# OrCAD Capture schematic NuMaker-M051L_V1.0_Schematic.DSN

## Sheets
1 Nu-Link2-Me: size A3; title: Nu-Link2-Me; rev: 1.0; company: CMHuang; note: Nu-Link2-Me
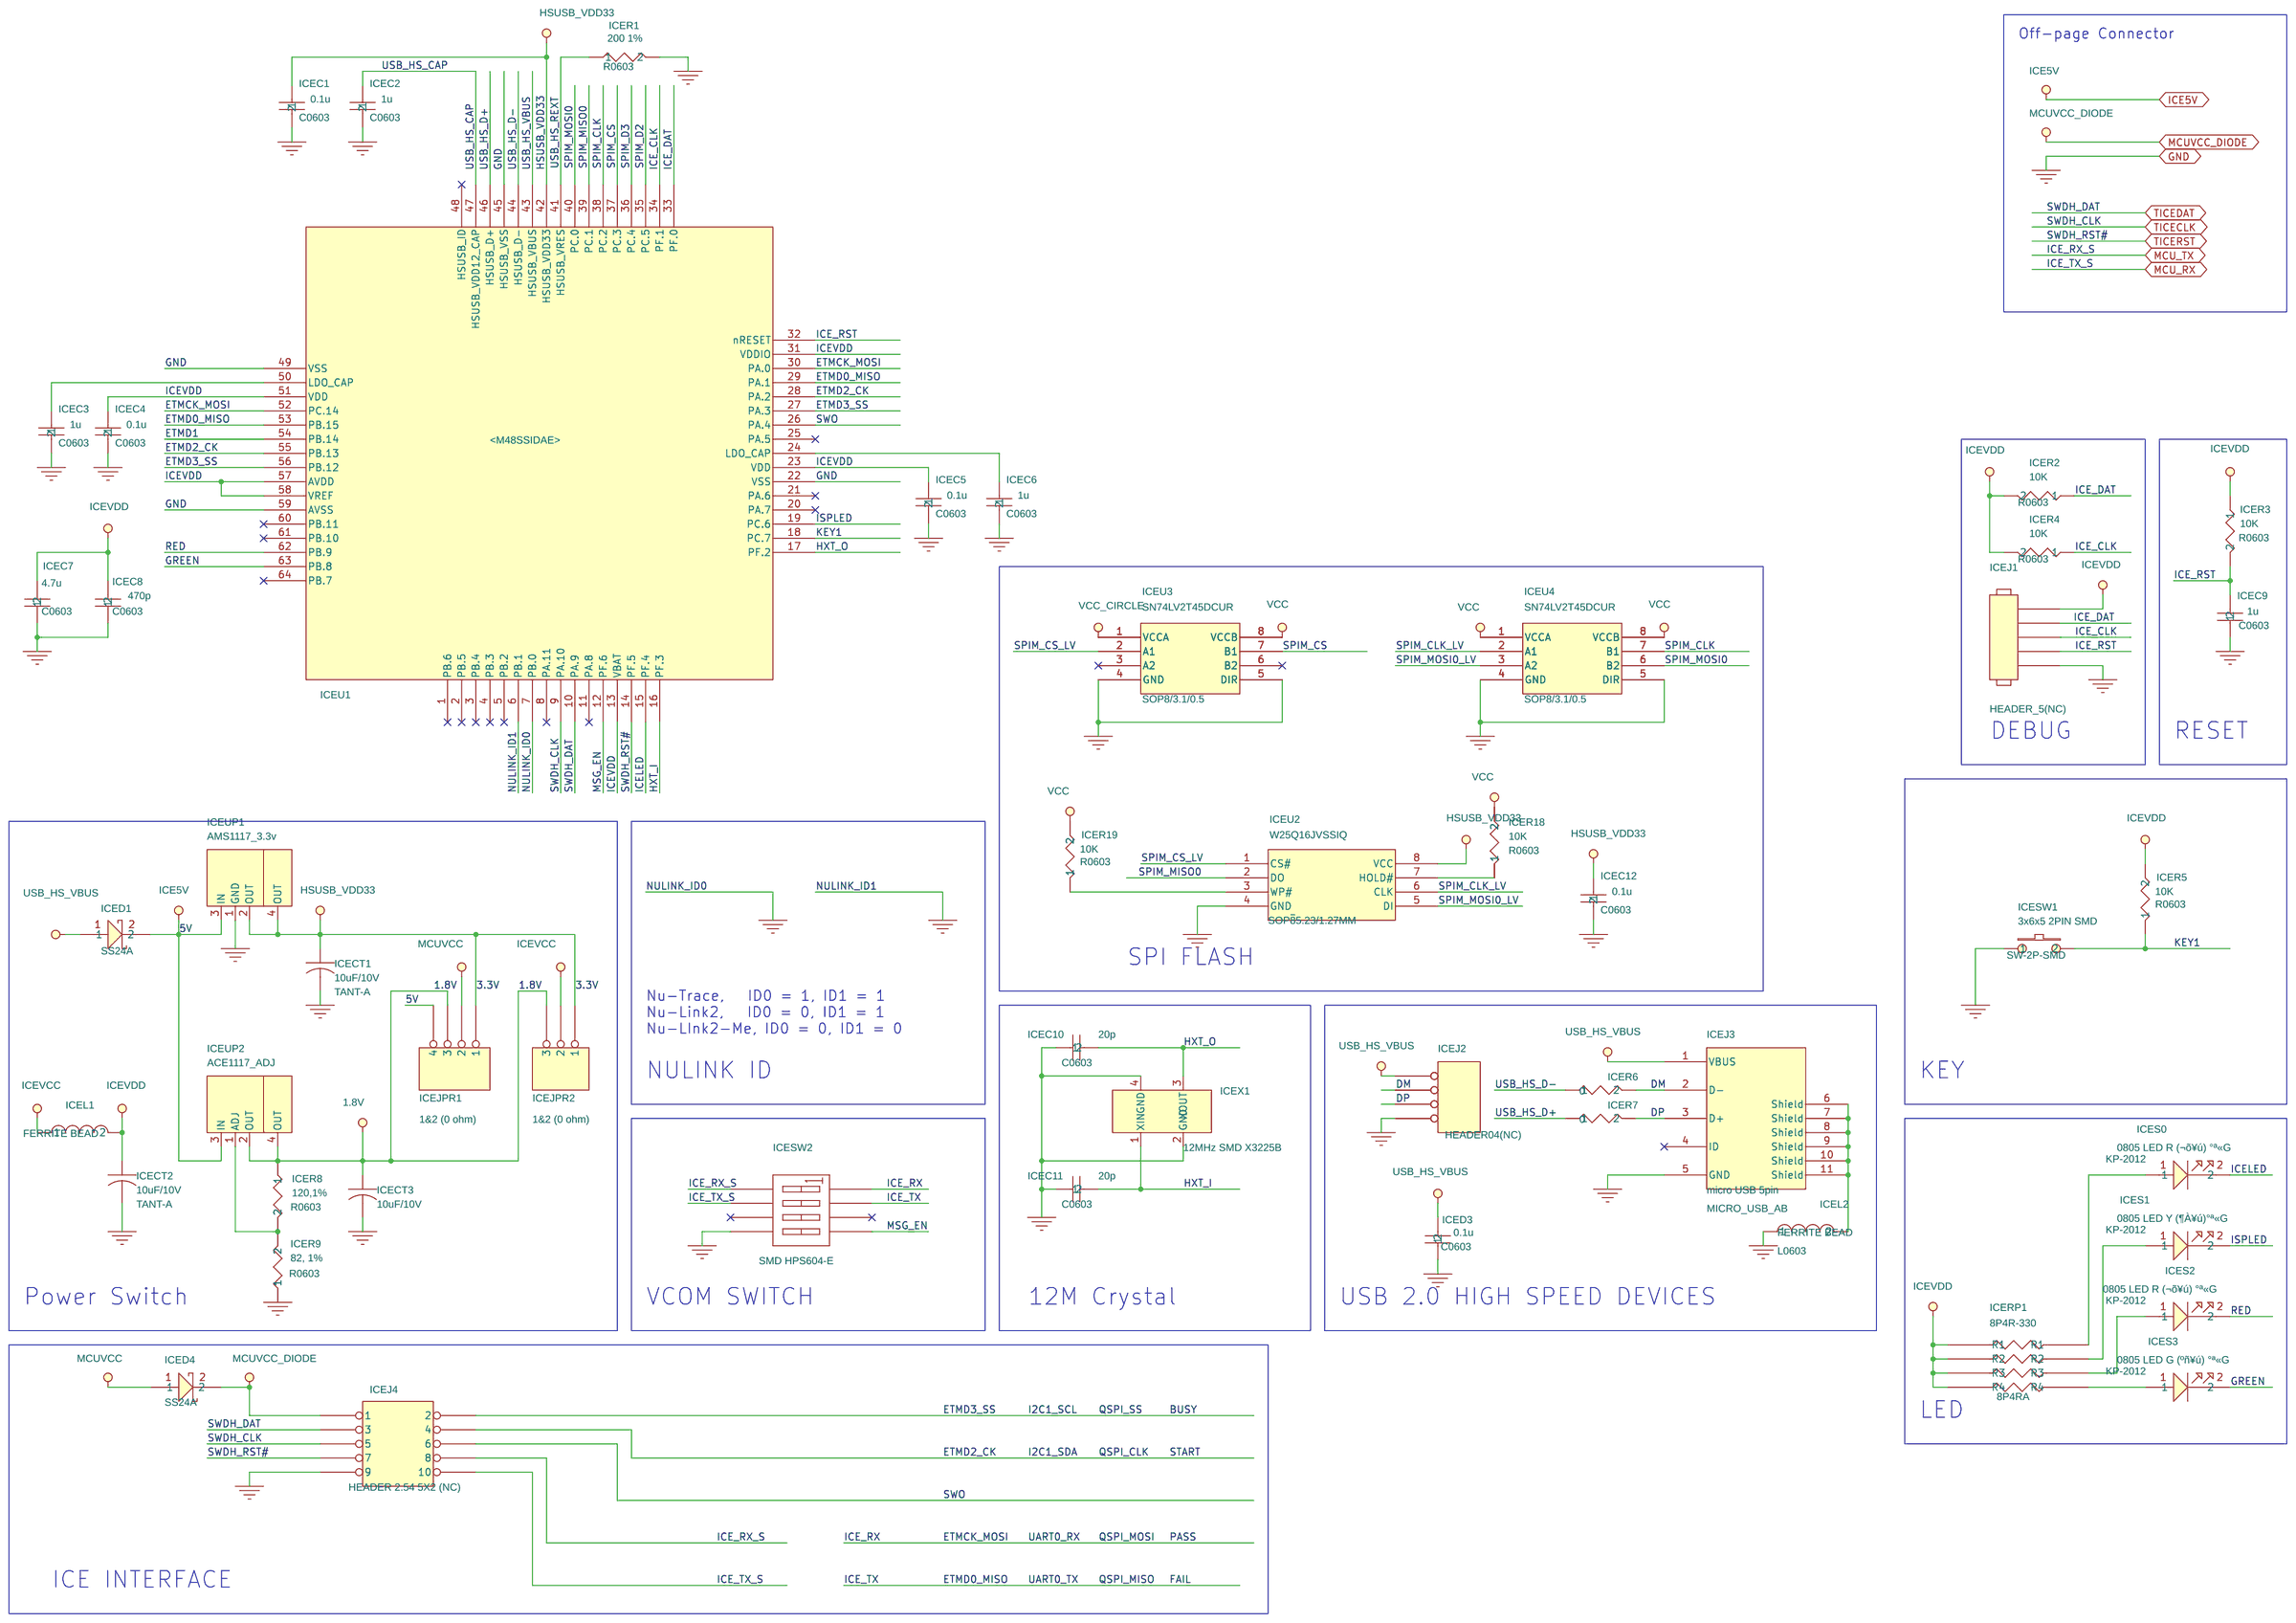
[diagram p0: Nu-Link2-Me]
2 M0516LDN: size Custom; title: M0516LDN; rev: v1.0; note: NuMaker-M051L
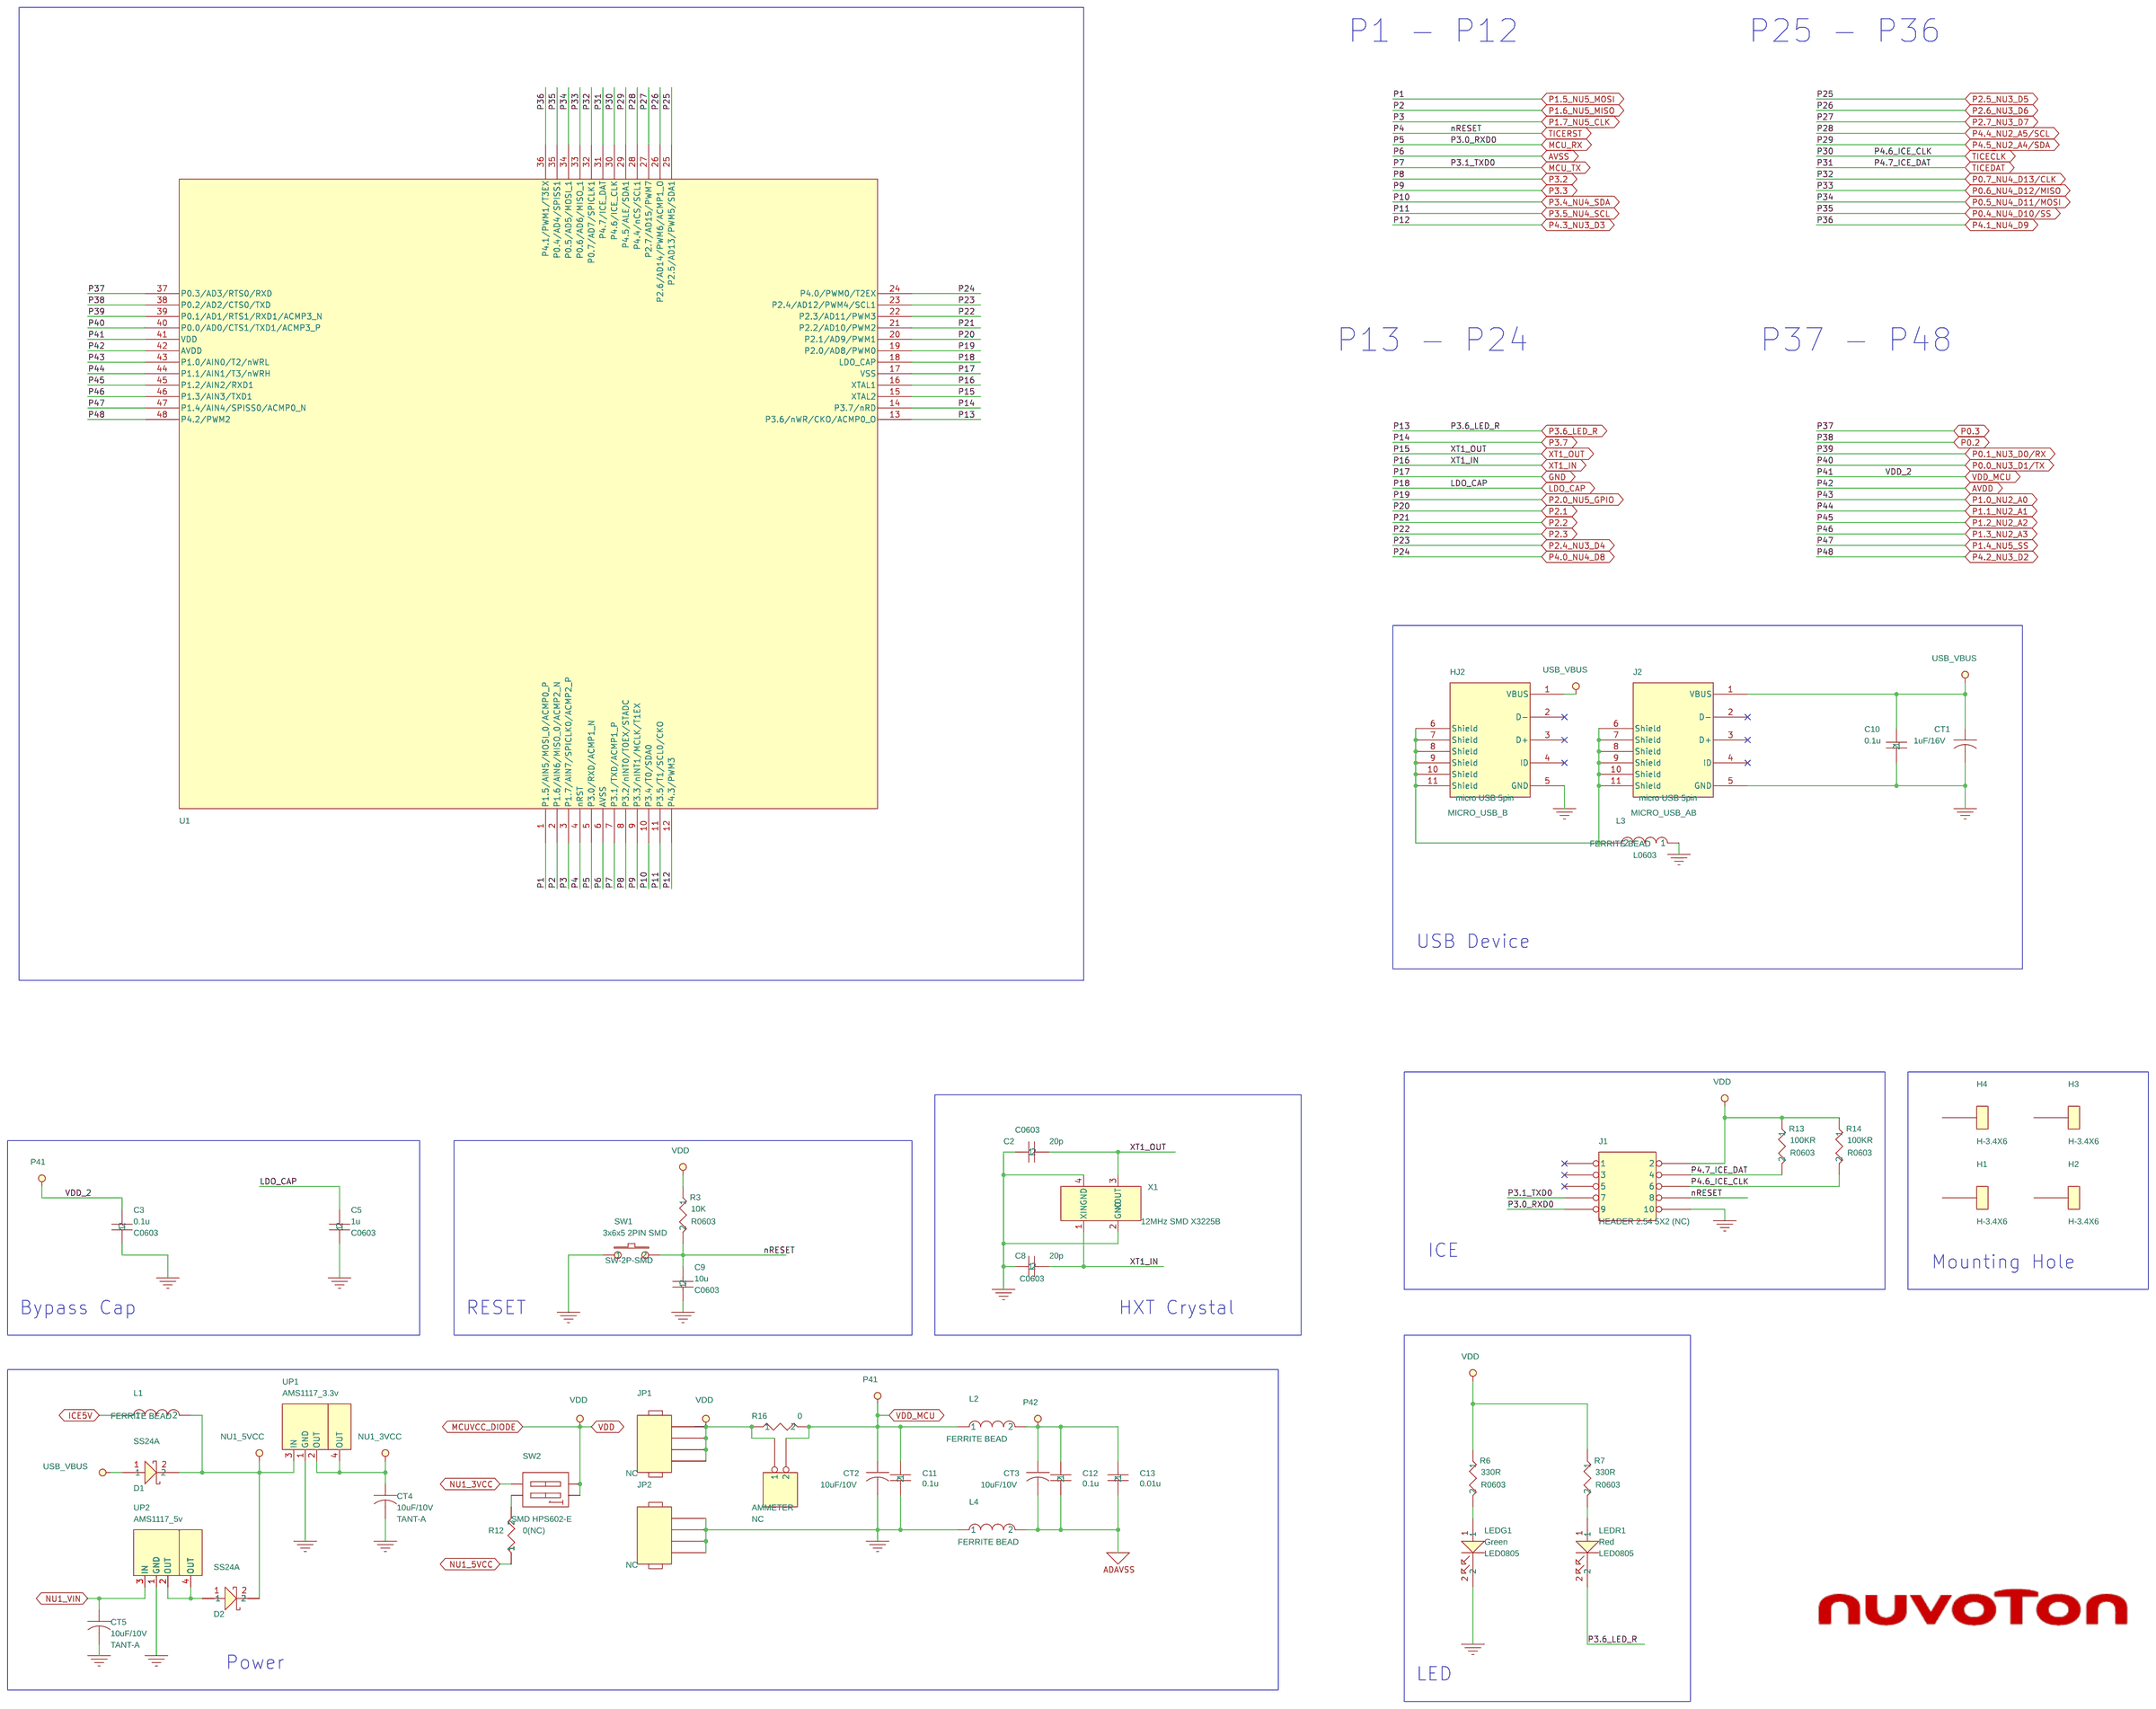
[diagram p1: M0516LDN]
3 Ext. Connector: size Custom; title: Ext. Connector; rev: v1.0; note: NuMaker-M051L
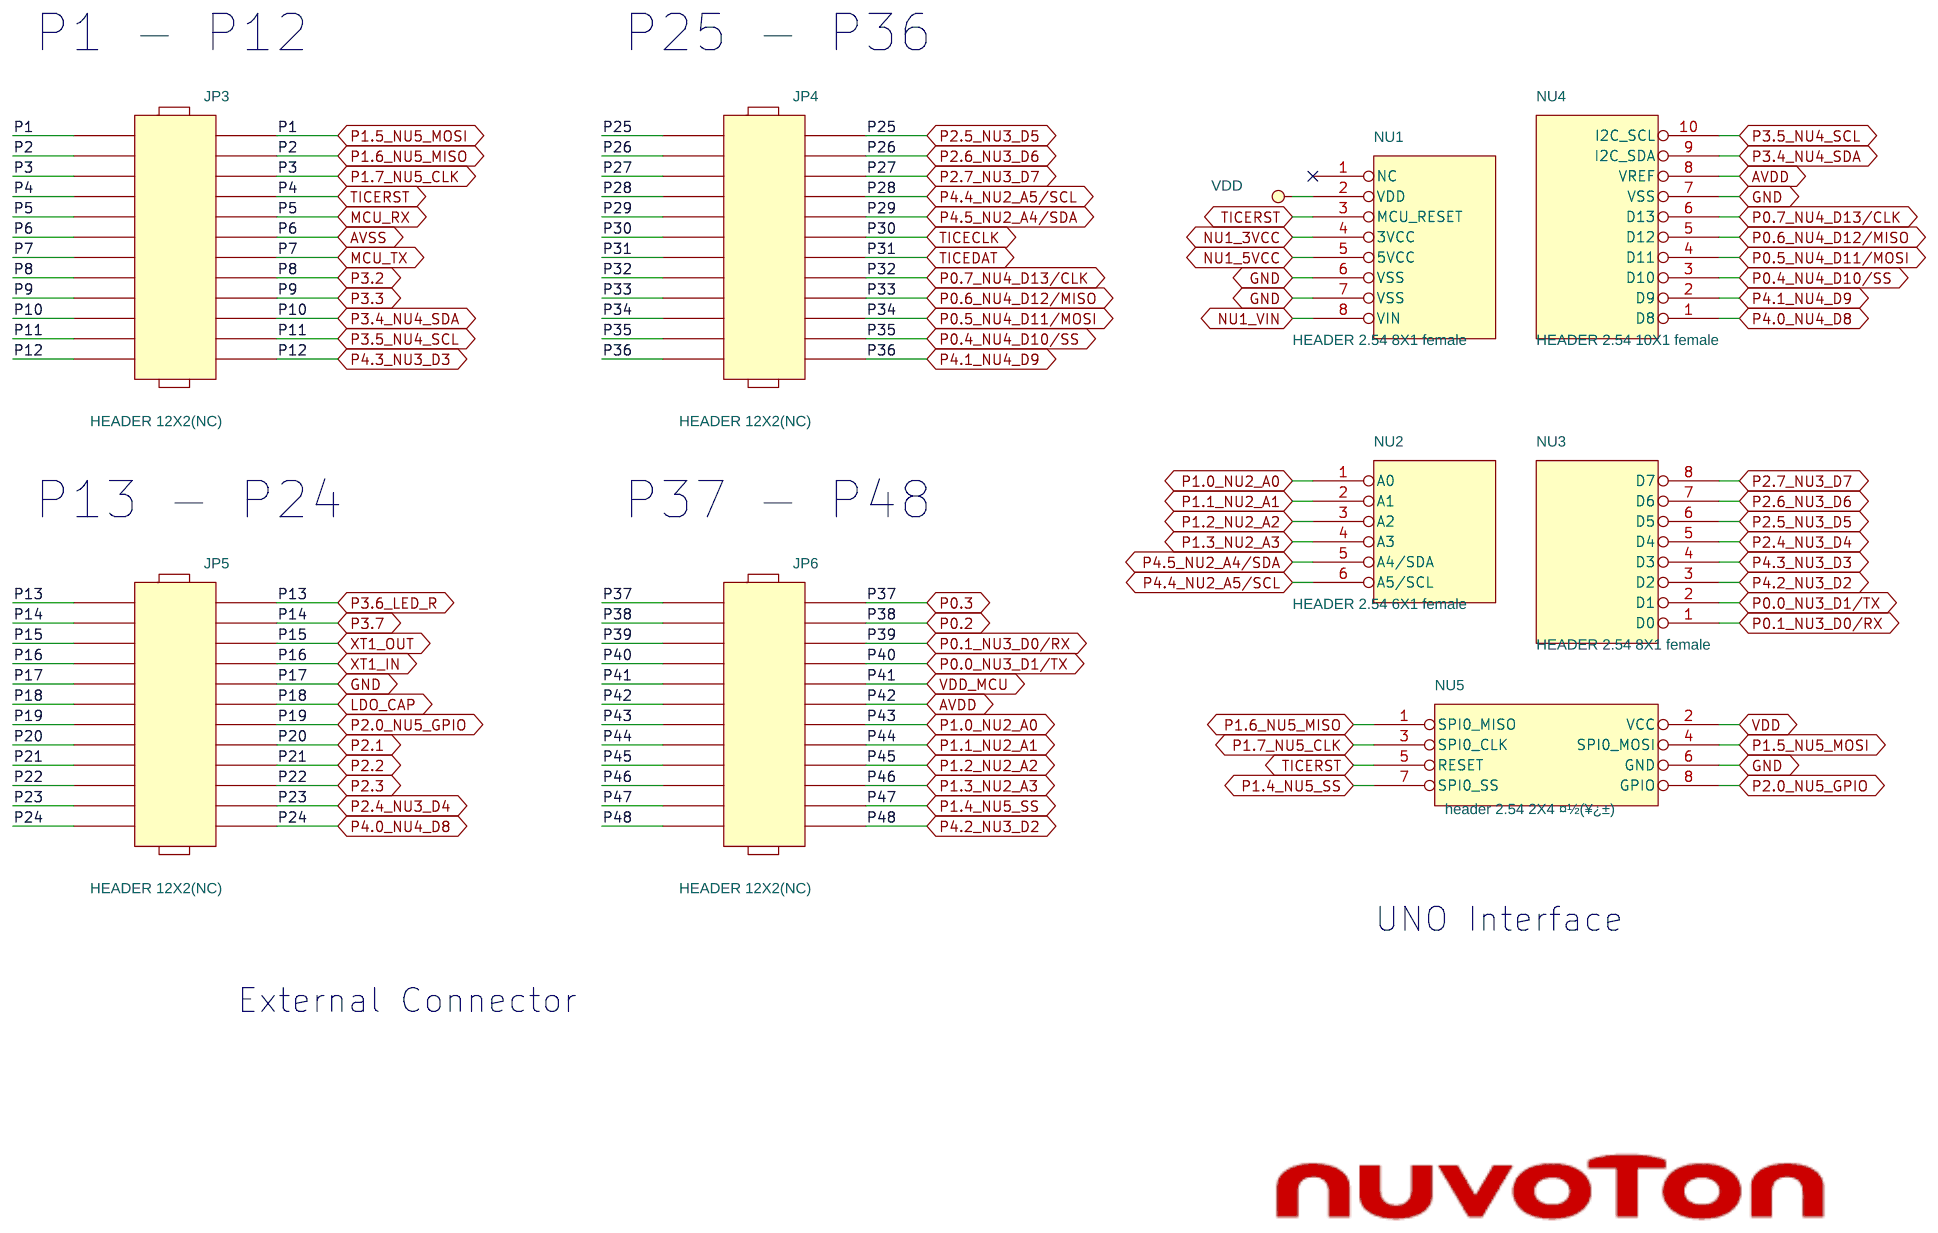
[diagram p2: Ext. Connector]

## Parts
sheet Ext. Connector
JP3  HEADER 12X2(NC)  [HEADER12x2/2.54]
JP4  HEADER 12X2(NC)  [HEADER12x2/2.54]
JP5  HEADER 12X2(NC)  [HEADER12x2/2.54]
JP6  HEADER 12X2(NC)  [HEADER12x2/2.54]
NU1  HEADER 2.54 8X1 female  [SIP-8P]
NU2  HEADER 2.54 6X1 female  [SIP-6P]
NU3  HEADER 2.54 8X1 female  [SIP-8P]
NU4  HEADER 2.54 10X1 female  [SIP-10P]
NU5  header 2.54 2X4 ¤½(¥¿­±)  [HEADER4X2]
sheet M0516LDN
AMMETER  NC  [HEADER2X1]
C2  20p  [C0603]
C3  0.1u  [C0603]
C5  1u  [C0603]
C8  20p  [C0603]
C9  10u  [C0603]
C10  0.1u  [C0603]
C11  0.1u  [C0603]
C12  0.1u  [C0603]
C13  0.01u  [C0603]
CT1  1uF/16V  [TANT-A]
CT2  10uF/10V  [TANT-A]
CT3  10uF/10V  [TANT-A]
CT4  10uF/10V  [TANT-A]
CT5  10uF/10V  [TANT-A]
D1  SS24A  [RB060L]
D2  SS24A  [RB060L]
H1  H-3.4X6  [H-3.4X6]
H2  H-3.4X6  [H-3.4X6]
H3  H-3.4X6  [H-3.4X6]
H4  H-3.4X6  [H-3.4X6]
HJ2  micro USB 5pin  [MICRO_USB_B]
J1  HEADER 2.54 5X2 (NC)  [HEADER5X2]
J2  micro USB 5pin  [MICRO_USB_AB]
JP1  NC  [header1x4]
JP2  NC  [header1x4]
L1  FERRITE BEAD  [L0603]
L2  FERRITE BEAD  [L0603]
L3  FERRITE BEAD  [L0603]
L4  FERRITE BEAD  [L0603]
LEDG1  Green  [LED0805]
LEDR1  Red  [LED0805]
R3  10K  [R0603]
R6  330R  [R0603]
R7  330R  [R0603]
R12  0(NC)  [R0603]
R13  100KR  [R0603]
R14  100KR  [R0603]
R16  0  [R0603]
SW1  3x6x5 2PIN SMD  [SW-2P-SMD]
SW2  SMD HPS602-E  [SW1X2]
U1  M0516LDN  [MCU_LQFP48_7X7mm]
UP1  AMS1117_3.3v  [SOT-223-1]
UP2  AMS1117_5v  [SOT-223-1]
X1  12MHz SMD X3225B  [CRYSTAL_SMD]
sheet Nu-Link2-Me
ICEC1  0.1u  [C0603]
ICEC2  1u  [C0603]
ICEC3  1u  [C0603]
ICEC4  0.1u  [C0603]
ICEC5  0.1u  [C0603]
ICEC6  1u  [C0603]
ICEC7  4.7u  [C0603]
ICEC8  470p  [C0603]
ICEC9  1u  [C0603]
ICEC10  20p  [C0603]
ICEC11  20p  [C0603]
ICEC12  0.1u  [C0603]
ICECT1  10uF/10V  [TANT-A]
ICECT2  10uF/10V  [TANT-A]
ICECT3  10uF/10V  [TANT-A]
ICED1  SS24A  [RB060L]
ICED3  0.1u  [C0603]
ICED4  SS24A  [RB060L]
ICEJ1  HEADER_5(NC)  [HEADER5X1]
ICEJ2  HEADER04(NC)  [HEADER04]
ICEJ3  micro USB 5pin  [MICRO_USB_AB]
ICEJ4  HEADER 2.54 5X2 (NC)  [HEADER5X2]
ICEJPR1  1&2 (0 ohm)  [R0603X3]
ICEJPR2  1&2 (0 ohm)  [R0603X2]
ICEL1  FERRITE BEAD  [L0603]
ICEL2  FERRITE BEAD  [L0603]
ICER1  200 1%  [R0603]
ICER2  10K  [R0603]
ICER3  10K  [R0603]
ICER4  10K  [R0603]
ICER5  10K  [R0603]
ICER6  0  [R0603]
ICER7  0  [R0603]
ICER8  120,1%  [R0603]
ICER9  82, 1%  [R0603]
ICER18  10K  [R0603]
ICER19  10K  [R0603]
ICERP1  8P4R-330  [8P4RA]
ICES0  0805 LED R (¬õ¥ú) °ª«G  [KP-2012]
ICES1  0805 LED Y (¶À¥ú)°ª«G  [KP-2012]
ICES2  0805 LED R (¬õ¥ú) °ª«G  [KP-2012]
ICES3  0805 LED G (ºñ¥ú) °ª«G  [KP-2012]
ICESW1  3x6x5 2PIN SMD  [SW-2P-SMD]
ICESW2  SMD HPS604-E  [SW1X4]
ICEU1  M48SSIDAE  [LQFP64_7x7_M48SSIDAE]
ICEU2  W25Q16JVSSIQ  [SOP8\5.23/1.27MM]
ICEU3  SN74LV2T45DCUR  [SOP8/3.1/0.5]
ICEU4  SN74LV2T45DCUR  [SOP8/3.1/0.5]
ICEUP1  AMS1117_3.3v  [SOT-223-1]
ICEUP2  ACE1117_ADJ  [SOT-223-1]
ICEX1  12MHz SMD X3225B  [CRYSTAL_SMD]

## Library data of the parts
JP3-JP6 = HEADER_12X2
NU1 = POWER_CONNECT_0
NU2 = ADC_CONNECT_0
NU3 = PWM0_CONNECT_0
NU4 = PWM1_CONNECT_1
NU5 = NuEdu_NU7
AMMETER = HEADER_2
C2 ICEC7 = CAP-C: Package: 0603
C3 = CAP-C_3: Package: 0603; element_no: C0004
C5 = CAP-C_1: Package: 0603; element_no: C0006
C8 = CAP-C_2: Package: 0603
C9 ICEC6 = CAP-C_4: Package: 0603; element_no: C0006
C10 = C_0.1u: element_no: C0004
C11 = C_0.1u_1: element_no: C0004
C12 = C_0.1u_3: element_no: C0004
C13 = C_0.1u_2: element_no: C0003
CT1 = C_1uF_16V
CT2-CT5 ICECT1-ICECT3 = C_10uF_10V
D1 ICED1 = D_SS24A
D2 ICED4 = D_SS24A_1
H1-H4 = TEST_POINT
HJ2 ICEJ3 J2 = micro_USB_5pin_0
ICEJ4 J1 = HEADER_5X2
JP1 JP2 = HEADER_4_v2
ICEL2 L1 = FERRITE_BEAD_1
L2 = FERRITE_BEAD_3
ICEL1 L3 = FERRITE_BEAD
L4 = FERRITE_BEAD_2
LEDG1 = LED_0_1: Package: KP-2012; Vendor: Kingbright
LEDR1 = LED_0: Package: KP-2012; Vendor: Kingbright
ICER2 R3 = R_0_2: Package: 0603
ICER1 R6 = R_0_4: Package: 0603
ICER5 R7 = R_0: Package: 0603
R12 = R_0_1
ICER8 R13 = R_0_3: Package: 0603
ICER3 R14 = R_0_5: Package: 0603
R16 = R_0_6
ICESW1 SW1 = SW_PUSHBUTTON_0
SW2 = SW_DIP-4_2
U1 = M0516LDN
ICEUP1 UP1 UP2 = TO-247_Regulator_10
ICEX1 X1 = Crystal_SMD_1
ICEC1 = CAP-C_9: Package: 0603; element_no: C0004
ICEC2 = CAP-C_10: Package: 0603; element_no: C0006
ICEC3 = CAP-C_12: Package: 0603; element_no: C0006
ICEC4 = CAP-C_2: Package: 0603; element_no: C0004
ICEC5 = CAP-C_5: Package: 0603; element_no: C0004
ICEC8 = CAP-C_7: Package: 0603
ICEC9 = CAP-C_6: Package: 0603; element_no: C0006
ICEC10 = CAP-C_3: Package: 0603
ICEC11 = CAP-C_11: Package: 0603
ICEC12 = CAP-C_8: Package: 0603; element_no: C0004
ICED3 = CAP-C_1: Package: 0603; element_no: C0004
ICEJ1 = HEADER_5
ICEJ2 = HEADER_4
ICEJPR1 = HEADER_3_0
ICEJPR2 = HEADER_3
ICER4 = R_0_7: Package: 0603
ICER6 = R_33
ICER7 = R_33_1
ICER9 = R_0_8: Package: 0603
ICER18 = R_0_6: Package: 0603
ICER19 = R_0_1: Package: 0603
ICERP1 = R-PACK8_0
ICES0 = LED_0_3: Vendor: Kingbright
ICES1 = LED_0: Vendor: Kingbright
ICES2 = LED_0_1: Vendor: Kingbright
ICES3 = LED_0_2: Vendor: Kingbright
ICESW2 = SW_DIP-4_SM
ICEU1 = M487SIDAE_0: M487SIDAE: <M48SSIDAE>
ICEU2 = W25P10_20_40_SOIC_0: Package: SOP8; Vendor: WINBOND
ICEU3 ICEU4 = SN74LV2T45
ICEUP2 = TO-247_Regulator_0

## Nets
1.8V: ICECT3.1 ICEJPR1.3 ICEJPR2.3 ICER8.1 ICEUP2.2(OUT) ICEUP2.4(OUT)
3.3V: ICEC1.1 ICEC12.1 ICECT1.1 ICEJPR1.1 ICEJPR2.1 ICER18.2 ICER19.2 ICEU1.42(HSUSB_VDD33) ICEU2.8(VCC) ICEU3.1(VCCA) ICEU4.1(VCCA) ICEUP1.2(OUT) ICEUP1.4(OUT)
AVDD: C12.1 C13.1 CT3.1 JP6.11 JP6.12 L2.2 NU4.8(VREF) U1.42(AVDD)
AVSS: C12.2 C13.2 CT3.2 JP3.11 JP3.12 L4.2 U1.6(AVSS)
GND: C2.1 C3.1 C5.1 C8.1 C9.1 C10.2 C11.2 CT1.2 CT2.2 CT4.2 CT5.2 HJ2.5(GND) ICEC1.2 ICEC2.2 ICEC3.2 ICEC4.2 ICEC5.2 ICEC6.2 ICEC7.1 ICEC8.1 ICEC9.1 ICEC10.1 ICEC11.1 ICEC12.2 ICECT1.2 ICECT2.2 ICECT3.2 ICED3.1 ICEJ1.5 ICEJ2.4 ICEJ3.5(GND) ICEJ4.9 ICEL2.1 ICER1.2 ICER9.1 ICESW1.1 ICESW2.4(A4) ICEU1.6(PB.1) ICEU1.7(PB.0) ICEU1.22(VSS) ICEU1.45(HSUSB_VSS) ICEU1.49(VSS) ICEU1.59(AVSS) ICEU2.4(GND) ICEU3.4(GND) ICEU3.5(DIR) ICEU4.4(GND) ICEU4.5(DIR) ICEUP1.1(GND) ICEX1.2(GND) ICEX1.4(GND) J1.10 J2.5(GND) JP2.1 JP2.2 JP2.3 JP2.4 JP5.9 JP5.10 L3.1 L4.1 LEDG1.2 NU1.6(VSS) NU1.7(VSS) NU4.7(VSS) NU5.6(GND) SW1.1 U1.17(VSS) UP1.1(GND) UP2.1(GND) X1.2(GND) X1.4(GND)
VDD: AMMETER.1 ICED4.2 ICEJ4.1 J1.2 JP1.1 JP1.2 JP1.3 JP1.4 NU1.2(VDD) NU5.2(VCC) R3.1 R6.1 R7.1 R13.1 R14.1 R16.1 SW2.3(B1) SW2.4(B2)
VDD_MCU: AMMETER.2 C3.2 C11.1 CT2.1 JP6.9 JP6.10 L2.1 R16.2 U1.41(VDD)
BUSY: ICEJ4.2 ICEU1.27(PA.3) ICEU1.56(PB.12)
DM: ICEJ2.2 ICEJ3.2(D-) ICER6.2
DP: ICEJ2.3 ICEJ3.3(D+) ICER7.2
ETMD1: ICEU1.54(PB.14)
ETMD2_CK: ICEJ4.4 ICEU1.28(PA.2) ICEU1.55(PB.13)
GREEN: ICES3.2 ICEU1.63(PB.8)
HXT_I: ICEC11.2 ICEU1.16(PF.3) ICEX1.1(XIN)
HXT_O: ICEC10.2 ICEU1.17(PF.2) ICEX1.3(XOUT)
ICE5V: ICED1.2 ICEJPR1.4 ICEUP1.3(IN) ICEUP2.3(IN) L1.1
ICE_CLK: ICEJ1.3 ICER4.1 ICEU1.34(PF.1)
ICE_DAT: ICEJ1.2 ICER2.1 ICEU1.33(PF.0)
ICE_RST: ICEC9.2 ICEJ1.4 ICER3.2 ICEU1.32(nRESET)
ICE_RX: ICESW2.8(B1) ICEU1.30(PA.0) ICEU1.52(PC.14)
ICE_TX: ICESW2.7(B2) ICEU1.29(PA.1) ICEU1.53(PB.15)
ICELED: ICES0.2 ICEU1.15(PF.4)
ICEVCC: ICEJPR2.2 ICEL1.1
ICEVDD: ICEC4.1 ICEC5.1 ICEC7.2 ICEC8.2 ICECT2.1 ICEJ1.1 ICEL1.2 ICER2.2 ICER3.1 ICER4.2 ICER5.2 ICERP1.1(R1) ICERP1.3(R2) ICERP1.5(R3) ICERP1.7(R4) ICEU1.13(VBAT) ICEU1.23(VDD) ICEU1.31(VDDIO) ICEU1.51(VDD) ICEU1.57(AVDD) ICEU1.58(VREF) ICEU3.8(VCCB) ICEU4.8(VCCB)
ISPLED: ICES1.2 ICEU1.19(PC.6)
KEY1: ICER5.1 ICESW1.2 ICEU1.18(PC.7)
LDO_CAP: C5.2 JP5.11 JP5.12 U1.18(LDO_CAP)
MCU_RX: ICEJ4.10 ICESW2.2(A2) J1.9 JP3.9 JP3.10 U1.5(P3.0/RXD/ACMP1_N)
MCU_TX: ICEJ4.8 ICESW2.1(A1) J1.7 JP3.13 JP3.14 U1.7(P3.1/TXD/ACMP1_P)
MCUVCC: ICED4.1 ICEJPR1.2
MSG_EN: ICESW2.5(B4) ICEU1.12(PF.6)
NU1_3VCC: CT4.1 NU1.4(3VCC) SW2.2(A2) UP1.2(OUT) UP1.4(OUT)
NU1_5VCC: D1.2 D2.2 L1.2 NU1.5(5VCC) R12.1 UP1.3(IN)
NU1_VIN: CT5.1 NU1.8(VIN) UP2.3(IN)
P0.0_NU3_D1/TX: JP6.7 JP6.8 NU3.2(D1) U1.40(P0.0/AD0/CTS1/TXD1/ACMP3_P)
P0.1_NU3_D0/RX: JP6.5 JP6.6 NU3.1(D0) U1.39(P0.1/AD1/RTS1/RXD1/ACMP3_N)
P0.2: JP6.3 JP6.4 U1.38(P0.2/AD2/CTS0/TXD)
P0.3: JP6.1 JP6.2 U1.37(P0.3/AD3/RTS0/RXD)
P0.4_NU4_D10/SS: JP4.21 JP4.22 NU4.3(D10) U1.35(P0.4/AD4/SPISS1)
P0.5_NU4_D11/MOSI: JP4.19 JP4.20 NU4.4(D11) U1.34(P0.5/AD5/MOSI_1)
P0.6_NU4_D12/MISO: JP4.17 JP4.18 NU4.5(D12) U1.33(P0.6/AD6/MISO_1)
P0.7_NU4_D13/CLK: JP4.15 JP4.16 NU4.6(D13) U1.32(P0.7/AD7/SPICLK1)
P1.0_NU2_A0: JP6.13 JP6.14 NU2.1(A0) U1.43(P1.0/AIN0/T2/nWRL)
P1.1_NU2_A1: JP6.15 JP6.16 NU2.2(A1) U1.44(P1.1/AIN1/T3/nWRH)
P1.2_NU2_A2: JP6.17 JP6.18 NU2.3(A2) U1.45(P1.2/AIN2/RXD1)
P1.3_NU2_A3: JP6.19 JP6.20 NU2.4(A3) U1.46(P1.3/AIN3/TXD1)
P1.4_NU5_SS: JP6.21 JP6.22 NU5.7(SPI0_SS) U1.47(P1.4/AIN4/SPISS0/ACMP0_N)
P1.5_NU5_MOSI: JP3.1 JP3.2 NU5.4(SPI0_MOSI) U1.1(P1.5/AIN5/MOSI_0/ACMP0_P)
P1.6_NU5_MISO: JP3.3 JP3.4 NU5.1(SPI0_MISO) U1.2(P1.6/AIN6/MISO_0/ACMP2_N)
P1.7_NU5_CLK: JP3.5 JP3.6 NU5.3(SPI0_CLK) U1.3(P1.7/AIN7/SPICLK0/ACMP2_P)
P2.0_NU5_GPIO: JP5.13 JP5.14 NU5.8(GPIO) U1.19(P2.0/AD8/PWM0)
P2.1: JP5.15 JP5.16 U1.20(P2.1/AD9/PWM1)
P2.2: JP5.17 JP5.18 U1.21(P2.2/AD10/PWM2)
P2.3: JP5.19 JP5.20 U1.22(P2.3/AD11/PWM3)
P2.4_NU3_D4: JP5.21 JP5.22 NU3.5(D4) U1.23(P2.4/AD12/PWM4/SCL1)
P2.5_NU3_D5: JP4.1 JP4.2 NU3.6(D5) U1.25(P2.5/AD13/PWM5/SDA1)
P2.6_NU3_D6: JP4.3 JP4.4 NU3.7(D6) U1.26(P2.6/AD14/PWM6/ACMP1_O)
P2.7_NU3_D7: JP4.5 JP4.6 NU3.8(D7) U1.27(P2.7/AD15/PWM7)
P3.2: JP3.15 JP3.16 U1.8(P3.2/nINT0/T0EX/STADC)
P3.3: JP3.17 JP3.18 U1.9(P3.3/nINT1/MCLK/T1EX)
P3.4_NU4_SDA: JP3.19 JP3.20 NU4.9(I2C_SDA) U1.10(P3.4/T0/SDA0)
P3.5_NU4_SCL: JP3.21 JP3.22 NU4.10(I2C_SCL) U1.11(P3.5/T1/SCL0/CKO)
P3.6_LED_R: JP5.1 JP5.2 LEDR1.2 U1.13(P3.6/nWR/CKO/ACMP0_O)
P3.7: JP5.3 JP5.4 U1.14(P3.7/nRD)
P4.0_NU4_D8: JP5.23 JP5.24 NU4.1(D8) U1.24(P4.0/PWM0/T2EX)
P4.1_NU4_D9: JP4.23 JP4.24 NU4.2(D9) U1.36(P4.1/PWM1/T3EX)
P4.2_NU3_D2: JP6.23 JP6.24 NU3.3(D2) U1.48(P4.2/PWM2)
P4.3_NU3_D3: JP3.23 JP3.24 NU3.4(D3) U1.12(P4.3/PWM3)
P4.4_NU2_A5/SCL: JP4.7 JP4.8 NU2.6(A5/SCL) U1.28(P4.4/nCS/SCL1)
P4.5_NU2_A4/SDA: JP4.9 JP4.10 NU2.5(A4/SDA) U1.29(P4.5/ALE/SDA1)
RED: ICES2.2 ICEU1.62(PB.9)
SPIM_CLK: ICEU1.38(PC.2) ICEU4.7(B1)
SPIM_CLK_LV: ICEU2.6(CLK) ICEU4.2(A1)
SPIM_CS: ICEU1.37(PC.3) ICEU3.7(B1)
SPIM_CS_LV: ICEU2.1(CS#) ICEU3.2(A1)
SPIM_D2: ICEU1.35(PC.5)
SPIM_D3: ICEU1.36(PC.4)
SPIM_MISO0: ICEU1.39(PC.1) ICEU2.2(DO)
SPIM_MOSI0: ICEU1.40(PC.0) ICEU4.6(B2)
SPIM_MOSI0_LV: ICEU2.5(DI) ICEU4.3(A2)
SWO: ICEJ4.6 ICEU1.26(PA.4)
TICECLK: ICEJ4.5 ICEU1.9(PA.10) J1.6 JP4.11 JP4.12 R14.2 U1.30(P4.6/ICE_CLK)
TICEDAT: ICEJ4.3 ICEU1.10(PA.9) J1.4 JP4.13 JP4.14 R13.2 U1.31(P4.7/ICE_DAT)
TICERST: C9.2 ICEJ4.7 ICEU1.14(PF.5) J1.8 JP3.7 JP3.8 NU1.3(MCU_RESET) NU5.5(RESET) R3.2 SW1.2 U1.4(nRST)
USB_HS_CAP: ICEC2.1 ICEU1.47(HSUSB_VDD12_CAP)
USB_HS_D+: ICER7.1 ICEU1.46(HSUSB_D+)
USB_HS_D-: ICER6.1 ICEU1.44(HSUSB_D-)
USB_HS_REXT: ICER1.1 ICEU1.41(HSUSB_VRES)
USB_HS_VBUS: ICED1.1 ICED3.2 ICEJ2.1 ICEJ3.1(VBUS) ICEU1.43(HSUSB_VBUS)
USB_VBUS: C10.1 CT1.1 D1.1 HJ2.1(VBUS) J2.1(VBUS)
XT1_IN: C8.2 JP5.7 JP5.8 U1.16(XTAL1) X1.1(XIN)
XT1_OUT: C2.2 JP5.5 JP5.6 U1.15(XTAL2) X1.3(XOUT)
N16825237: LEDG1.1 R6.2
N16825240: LEDR1.1 R7.2
N16840819: ICEC6.1 ICEU1.24(LDO_CAP)
N16840960: ICEC3.1 ICEU1.50(LDO_CAP)
N17019924: ICER8.2 ICER9.2 ICEUP2.1(ADJ)
N17029977: ICERP1.8(R4) ICES3.1
N17029979: ICERP1.6(R3) ICES2.1
N17030004: ICERP1.4(R2) ICES1.1
N17030010: ICERP1.2(R1) ICES0.1
N17042369: ICEJ3.6(Shield) ICEJ3.7(Shield) ICEJ3.8(Shield) ICEJ3.9(Shield) ICEJ3.10(Shield) ICEJ3.11(Shield) ICEL2.2
N17155328: ICER18.1 ICEU2.7(HOLD#)
N17155343: ICER19.1 ICEU2.3(WP#)
N17239886: R12.2 SW2.1(A1)
N17239930: D2.1 UP2.2(OUT) UP2.4(OUT)
N17242099: HJ2.6(Shield) HJ2.7(Shield) HJ2.8(Shield) HJ2.9(Shield) HJ2.10(Shield) HJ2.11(Shield) J2.6(Shield) J2.7(Shield) J2.8(Shield) J2.9(Shield) J2.10(Shield) J2.11(Shield) L3.2

Not connected (* = marked no-connect by the designer): H1 1; H2 1; H3 1; H4 1; HJ2 2(D-)* 3(D+)* 4(ID)*; ICEJ3 4(ID)*; ICESW2 3(A3)* 6(B3)*; ICEU1 1(PB.6)* 2(PB.5)* 3(PB.4)* 4(PB.3)* 5(PB.2)* 8(PA.11)* 11(PA.8)* 20(PA.7)* 21(PA.6)* 25(PA.5)* 48(HSUSB_ID)* 60(PB.11)* 61(PB.10)* 64(PB.7)*; ICEU3 3(A2)* 6(B2)*; J1 1* 3* 5*; J2 2(D-)* 3(D+)* 4(ID)*; NU1 1(NC)*

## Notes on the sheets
sheet 1
- Off-page Connector
- DEBUG
- RESET
- SPI FLASH
- Nu-Trace,   ID0 = 1, ID1 = 1
  Nu-Link2,   ID0 = 0, ID1 = 1
  Nu-LInk2-Me, ID0 = 0, ID1 = 0
- NULINK ID
- KEY
- Power Switch
- VCOM SWITCH
- 12M Crystal
- USB 2.0 HIGH SPEED DEVICES
- LED
- ICE INTERFACE
sheet 2
- P1 - P12
- P25 - P36
- P13 - P24
- P37 - P48
- USB Device
- ICE
- Mounting Hole
- Bypass Cap
- RESET
- HXT Crystal
- Power
- LED
sheet 3
- P1 - P12
- P25 - P36
- P13 - P24
- P37 - P48
- UNO Interface
- External Connector
